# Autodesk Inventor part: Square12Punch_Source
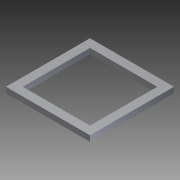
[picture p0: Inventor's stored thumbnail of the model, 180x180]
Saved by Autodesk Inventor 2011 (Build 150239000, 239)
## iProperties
Created: 2007-02
Part Number: Square12Punch_Source
Material: Default
Document SubType Name: Sheet Metal
Designer: Autodesk, Inc.
Mass: 0.081 g
Surface Area: 2.7 cm^2
Volume: 0.081 cm^3
Density: 1 g/cm^3
Sheet Metal Rule: 1 mm
Author: Autodesk, Inc.
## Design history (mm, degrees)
node "Face1"
  sketch "Sketch1"
    geometry: L1 (-7.5, 7.5)-(7.5, 7.5); L2 (7.5, 7.5)-(7.5, -7.5); L3 (7.5, -7.5)-(-7.5, -7.5); L4 (-7.5, -7.5)-(-7.5, 7.5); L5 (-7.5, 7.5)-(7.5, -7.5); 2 further points
    constraints: 10 end point, 2 parallel, 1 coincident, 1 horizontal, 1 midpoint, 1 perpendicular
    dimensions: "d0" = 15 distance of L2.end L3.end; "d1" = 15 distance of L1.end L2.end (= d0)
sketch "Sketch2"
  geometry: L1 (-6, 6)-(6, 6); L2 (6, 6)-(6, -6); L3 (6, -6)-(-6, -6); L4 (-6, -6)-(-6, 6); L5 (-6, -6)-(6, 6); 3 further points
  constraints: 10 end point, 2 coincident, 2 parallel, 1 horizontal, 1 midpoint, 1 perpendicular
  dimensions: "d3" = 12 distance of L2.end L3.end; "d4" = 12 distance of L1.end L2.end (= d3)
cut "Cut1" sketch "Sketch2" dims "d5" = 1 (= Thickness), "d6" = 0
body "Solid1"
face "Plate1" dims "Thickness" = 1
other parameters: "BendRadius" = 0.5, "BendReliefWidth" = 1 (= Thickness), "BendReliefDepth" = 0.5 (= 0.5 x Thickness), "CornerReliefSize" = 4 (= 4 x Thickness), "SeamGap" = 0.01, "MinimumRemnant" = 2 (= 2 x Thickness), "TransitionRadius" = 0.5 (= BendRadius), "JacobiRadiusSize" = 1 (= Thickness), "d2" = 0.5 (= BendRadius), "GapSize" = 1 (= Thickness)
